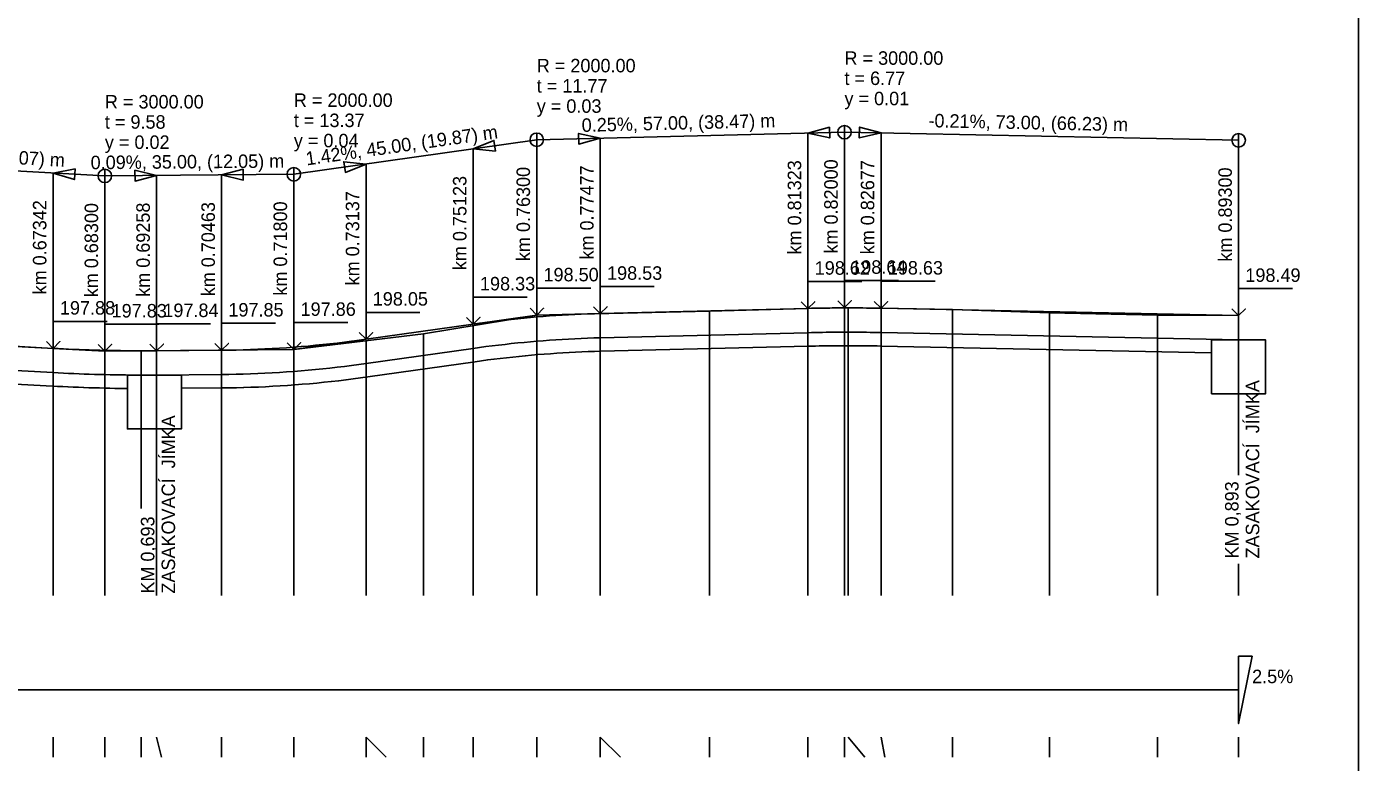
# Model space of a CAD drawing. Extents: x -51 to 53, y -74 to 15.
# Drawn here: x 28.41 to 53.08, y -60.64 to -47 of the extents above; entities that cross this region are included whole.
import ezdxf

# ---------------------------------------------------------------- set-up
doc = ezdxf.new("R2010")
doc.units = 0
for name, color, linetype in [('Implicitní', 7, 'Continuous'), ('KONSTRUKCE_L', 7, 'Continuous'), ('KOTY_L', 7, 'Continuous'), ('Nová vrstva (0)', 7, 'Continuous'), ('PR_SKLON_L', 7, 'Continuous'), ('PR_SKLON_T', 7, 'Continuous'), ('SKLON_POMERY', 7, 'Continuous'), ('TEREN_L', 7, 'Continuous'), ('V_POLYGON', 7, 'Continuous'), ('V_POLYGON_ZO', 7, 'Continuous')]:
    doc.layers.add(name, color=color, linetype=linetype)

msp = doc.modelspace()

# ---------------------------------------------------------------- linework, layer by layer
at = {"layer": 'Implicitní'}
msp.add_lwpolyline([(-51.392, -44.246), (53.079, -44.246), (53.079, -73.946), (-51.392, -73.946)], close=True, dxfattribs=at)
at = {"layer": 'KONSTRUKCE_L'}
for p, q in [((38.566, -52.789), (38.684, -52.784)), ((38.684, -52.784), (38.801, -52.779)), ((38.801, -52.779), (38.919, -52.776)), ((38.919, -52.776), (39.037, -52.772)), ((39.037, -52.772), (42.883, -52.678)), ((42.883, -52.678), (42.951, -52.676)), ((42.951, -52.676), (43.019, -52.675)), ((43.019, -52.675), (43.086, -52.674)), ((43.086, -52.674), (43.154, -52.672)), ((43.154, -52.672), (43.222, -52.671)), ((43.222, -52.671), (43.289, -52.671)), ((43.289, -52.671), (43.357, -52.67)), ((43.357, -52.67), (43.425, -52.669)), ((43.425, -52.669), (43.492, -52.669)), ((43.492, -52.669), (43.56, -52.669)), ((43.56, -52.669), (43.628, -52.669)), ((43.628, -52.669), (43.695, -52.669)), ((43.695, -52.669), (43.763, -52.669)), ((43.763, -52.669), (43.831, -52.669)), ((43.831, -52.669), (43.898, -52.67)), ((43.898, -52.67), (43.966, -52.671)), ((43.966, -52.671), (44.034, -52.672)), ((44.034, -52.672), (44.101, -52.673)), ((44.101, -52.673), (44.169, -52.674)), ((44.169, -52.674), (44.237, -52.675)), ((44.237, -52.675), (50.86, -52.811)), ((34.697, -53.251), (36.683, -52.969)), ((36.683, -52.969), (36.801, -52.952)), ((36.801, -52.952), (36.919, -52.936)), ((36.919, -52.936), (37.036, -52.921)), ((37.036, -52.921), (37.154, -52.907)), ((37.154, -52.907), (37.272, -52.894)), ((37.272, -52.894), (37.389, -52.881)), ((37.389, -52.881), (37.507, -52.868)), ((37.507, -52.868), (37.625, -52.857)), ((37.625, -52.857), (37.742, -52.846)), ((37.742, -52.846), (37.86, -52.836)), ((37.86, -52.836), (37.978, -52.826)), ((37.978, -52.826), (38.095, -52.818)), ((38.095, -52.818), (38.213, -52.809)), ((38.213, -52.809), (38.331, -52.802)), ((38.331, -52.802), (38.448, -52.795)), ((38.448, -52.795), (38.566, -52.789)), ((34.429, -53.287), (34.563, -53.27)), ((34.563, -53.27), (34.697, -53.251)), ((26.694, -53.296), (28.902, -53.418)), ((28.902, -53.418), (28.997, -53.423)), ((28.997, -53.423), (29.093, -53.428)), ((29.093, -53.428), (29.189, -53.433)), ((29.189, -53.433), (29.285, -53.437)), ((29.285, -53.437), (29.381, -53.441)), ((29.381, -53.441), (29.477, -53.444)), ((29.477, -53.444), (29.572, -53.448)), ((29.572, -53.448), (29.668, -53.451)), ((29.668, -53.451), (29.764, -53.453)), ((29.764, -53.453), (29.86, -53.456)), ((29.86, -53.456), (29.956, -53.458)), ((29.956, -53.458), (30.052, -53.46)), ((30.052, -53.46), (30.148, -53.461)), ((30.148, -53.461), (30.243, -53.462)), ((30.243, -53.462), (30.339, -53.463)), ((30.339, -53.463), (30.435, -53.464)), ((30.435, -53.464), (30.531, -53.464)), ((30.531, -53.464), (30.627, -53.464)), ((30.627, -53.464), (30.723, -53.464)), ((30.723, -53.464), (30.818, -53.463)), ((30.818, -53.463), (32.023, -53.453)), ((32.023, -53.453), (32.157, -53.451)), ((32.157, -53.451), (32.291, -53.449)), ((32.291, -53.449), (32.424, -53.445)), ((32.424, -53.445), (32.558, -53.441)), ((32.558, -53.441), (32.692, -53.436)), ((32.692, -53.436), (32.825, -53.43)), ((32.825, -53.43), (32.959, -53.423)), ((32.959, -53.423), (33.093, -53.415)), ((33.093, -53.415), (33.226, -53.406)), ((33.226, -53.406), (33.36, -53.397)), ((33.36, -53.397), (33.494, -53.386)), ((33.494, -53.386), (33.627, -53.375)), ((33.627, -53.375), (33.761, -53.362)), ((33.761, -53.362), (33.895, -53.349)), ((33.895, -53.349), (34.028, -53.335)), ((34.028, -53.335), (34.162, -53.32)), ((34.162, -53.32), (34.296, -53.304)), ((34.296, -53.304), (34.429, -53.287))]:
    msp.add_line(p, q, dxfattribs=at)
at = {"layer": 'KOTY_L'}
for p, q in [((41.06, -57.551), (41.06, -52.281)), ((42.883, -57.551), (42.883, -52.23)), ((43.56, -57.551), (43.56, -52.211)), ((43.628, -57.551), (43.628, -52.213)), ((44.237, -57.551), (44.237, -52.225)), ((45.56, -57.551), (45.56, -52.251)), ((37.86, -57.551), (37.86, -52.351)), ((39.037, -57.551), (39.037, -52.325)), ((39.037, -57.551), (39.037, -52.325)), ((47.36, -57.551), (47.36, -52.311)), ((49.36, -57.551), (49.36, -52.351)), ((50.86, -55.319), (50.86, -52.361)), ((35.76, -57.551), (35.76, -52.701)), ((36.683, -57.551), (36.683, -52.547)), ((28.902, -57.551), (28.902, -52.971)), ((29.86, -57.551), (29.86, -53.021)), ((30.531, -55.937), (30.531, -53.015)), ((30.818, -57.551), (30.818, -53.013)), ((32.023, -57.551), (32.023, -53.003)), ((33.36, -57.551), (33.36, -52.991)), ((34.697, -57.551), (34.697, -52.83)), ((34.697, -57.551), (34.697, -52.83)), ((50.86, -57.551), (50.86, -56.964)), ((28.902, -60.551), (28.902, -60.176)), ((29.86, -60.551), (29.86, -60.176)), ((30.531, -60.551), (30.531, -60.176)), ((30.906, -60.551), (30.818, -60.176)), ((32.023, -60.551), (32.023, -60.176)), ((33.36, -60.551), (33.36, -60.176)), ((34.697, -60.551), (34.697, -60.176)), ((35.072, -60.551), (34.697, -60.176)), ((35.76, -60.551), (35.76, -60.176)), ((36.683, -60.551), (36.683, -60.176)), ((37.86, -60.551), (37.86, -60.176)), ((39.037, -60.551), (39.037, -60.176)), ((39.412, -60.551), (39.037, -60.176)), ((41.06, -60.551), (41.06, -60.176)), ((42.883, -60.551), (42.883, -60.176)), ((43.56, -60.551), (43.56, -60.176)), ((43.935, -60.551), (43.628, -60.176)), ((44.31, -60.551), (44.237, -60.176)), ((45.56, -60.551), (45.56, -60.176)), ((47.36, -60.551), (47.36, -60.176)), ((49.36, -60.551), (49.36, -60.176)), ((50.86, -60.551), (50.86, -60.176))]:
    msp.add_line(p, q, dxfattribs=at)
at = {"layer": 'Nová vrstva (0)'}
for p, q in [((38.577, -53.039), (38.695, -53.034)), ((38.693, -53.034), (38.811, -53.029)), ((38.81, -53.029), (38.927, -53.025)), ((38.926, -53.025), (39.043, -53.022)), ((39.043, -53.022), (42.889, -52.928)), ((42.889, -52.928), (42.957, -52.926)), ((42.956, -52.926), (43.024, -52.925)), ((43.023, -52.925), (43.091, -52.923)), ((43.091, -52.923), (43.158, -52.922)), ((43.158, -52.922), (43.225, -52.921)), ((43.225, -52.921), (43.292, -52.921)), ((43.292, -52.921), (43.359, -52.92)), ((43.359, -52.92), (43.427, -52.919)), ((43.426, -52.919), (43.494, -52.919)), ((43.493, -52.919), (43.561, -52.919)), ((43.56, -52.919), (43.628, -52.919)), ((43.627, -52.919), (43.695, -52.919)), ((43.694, -52.919), (43.762, -52.919)), ((43.762, -52.919), (43.829, -52.919)), ((43.829, -52.919), (43.896, -52.92)), ((43.896, -52.92), (43.963, -52.921)), ((43.963, -52.921), (44.03, -52.922)), ((44.03, -52.922), (44.098, -52.923)), ((44.097, -52.923), (44.165, -52.924)), ((44.164, -52.924), (44.232, -52.925)), ((44.232, -52.925), (50.36, -53.051)), ((34.732, -53.499), (36.719, -53.216)), ((36.718, -53.216), (36.836, -53.2)), ((36.834, -53.2), (36.952, -53.184)), ((36.95, -53.184), (37.068, -53.169)), ((37.067, -53.17), (37.184, -53.155)), ((37.183, -53.155), (37.3, -53.142)), ((37.299, -53.142), (37.417, -53.129)), ((37.415, -53.129), (37.533, -53.117)), ((37.531, -53.117), (37.649, -53.106)), ((37.648, -53.106), (37.765, -53.095)), ((37.764, -53.095), (37.882, -53.085)), ((37.88, -53.085), (37.998, -53.076)), ((37.996, -53.076), (38.114, -53.067)), ((38.112, -53.067), (38.23, -53.059)), ((38.229, -53.059), (38.346, -53.052)), ((38.345, -53.052), (38.463, -53.045)), ((38.461, -53.045), (38.579, -53.039)), ((34.462, -53.535), (34.596, -53.518)), ((34.597, -53.517), (34.731, -53.499)), ((26.681, -53.546), (28.888, -53.668)), ((28.888, -53.668), (28.984, -53.673)), ((28.985, -53.673), (29.081, -53.678)), ((29.081, -53.678), (29.177, -53.682)), ((29.178, -53.682), (29.274, -53.687)), ((29.275, -53.687), (29.371, -53.691)), ((29.371, -53.691), (29.467, -53.694)), ((29.468, -53.694), (29.564, -53.698)), ((29.565, -53.698), (29.66, -53.701)), ((29.661, -53.701), (29.757, -53.703)), ((29.758, -53.703), (29.854, -53.706)), ((29.855, -53.706), (29.95, -53.708)), ((29.951, -53.708), (30.047, -53.71)), ((30.048, -53.71), (30.144, -53.711)), ((30.144, -53.711), (30.279, -53.713)), ((31.279, -53.709), (32.026, -53.703)), ((32.026, -53.703), (32.16, -53.701)), ((32.162, -53.701), (32.295, -53.699)), ((32.297, -53.698), (32.431, -53.695)), ((32.432, -53.695), (32.566, -53.691)), ((32.568, -53.691), (32.701, -53.686)), ((32.703, -53.685), (32.837, -53.679)), ((32.838, -53.679), (32.972, -53.672)), ((32.974, -53.672), (33.107, -53.664)), ((33.109, -53.664), (33.243, -53.656)), ((33.244, -53.656), (33.378, -53.646)), ((33.38, -53.646), (33.513, -53.635)), ((33.515, -53.635), (33.649, -53.624)), ((33.65, -53.624), (33.784, -53.611)), ((33.786, -53.611), (33.919, -53.598)), ((33.921, -53.598), (34.054, -53.584)), ((34.056, -53.583), (34.19, -53.568)), ((34.191, -53.568), (34.325, -53.552)), ((34.327, -53.552), (34.46, -53.535))]:
    msp.add_line(p, q, dxfattribs=at)
for points in [[(50.36, -52.811), (51.36, -52.811), (51.36, -53.811), (50.36, -53.811)], [(30.279, -53.463), (31.279, -53.463), (31.279, -54.463), (30.279, -54.463)]]:
    msp.add_lwpolyline(points, close=True, dxfattribs=at)
at = {"layer": 'PR_SKLON_L'}
msp.add_line((8.36, -59.301), (50.86, -59.301), dxfattribs=at)
msp.add_lwpolyline([(50.86, -59.301), (50.86, -58.676), (51.11, -58.676), (50.86, -59.926)], close=True, dxfattribs=at)
at = {"layer": 'SKLON_POMERY'}
for p, q in [((43.56, -48.961), (43.56, -48.836)), ((37.86, -49.101), (43.56, -48.961)), ((37.86, -49.101), (37.86, -48.976)), ((39.037, -52.322), (39.037, -49.072)), ((42.883, -52.228), (42.883, -48.978)), ((43.56, -52.211), (43.56, -48.961)), ((43.56, -48.961), (50.86, -49.111)), ((44.237, -52.225), (44.237, -48.975)), ((50.86, -49.111), (50.86, -48.986)), ((33.36, -49.741), (37.86, -49.101)), ((36.683, -52.519), (36.683, -49.269)), ((37.86, -52.351), (37.86, -49.101)), ((50.86, -52.361), (50.86, -49.111)), ((25.16, -49.511), (29.86, -49.771)), ((34.697, -52.801), (34.697, -49.551)), ((28.902, -52.968), (28.902, -49.718)), ((29.86, -49.771), (29.86, -49.646)), ((29.86, -49.771), (33.36, -49.741)), ((29.86, -53.021), (29.86, -49.771)), ((30.818, -53.013), (30.818, -49.763)), ((32.023, -53.003), (32.023, -49.753)), ((33.36, -49.741), (33.36, -49.616)), ((33.36, -52.991), (33.36, -49.741))]:
    msp.add_line(p, q, dxfattribs=at)
for points in [[(39.037, -49.072), (38.639, -49.182), (38.634, -48.982), (39.037, -49.072)], [(42.883, -48.978), (43.286, -49.068), (43.281, -48.868), (42.883, -48.978)], [(44.237, -48.975), (43.835, -49.067), (43.839, -48.867), (44.237, -48.975)], [(36.683, -49.269), (37.093, -49.311), (37.065, -49.113), (36.683, -49.269)], [(34.697, -49.551), (34.315, -49.706), (34.286, -49.508), (34.697, -49.551)], [(28.902, -49.718), (29.296, -49.84), (29.307, -49.64), (28.902, -49.718)], [(30.818, -49.763), (30.419, -49.866), (30.418, -49.666), (30.818, -49.763)], [(32.023, -49.753), (32.424, -49.849), (32.423, -49.649), (32.023, -49.753)]]:
    msp.add_lwpolyline(points, close=True, dxfattribs=at)
for points in [[(42.758, -52.103), (42.883, -52.228), (43.008, -52.103), (42.883, -52.228), (42.883, -51.728), (43.883, -51.728)], [(43.435, -52.086), (43.56, -52.211), (43.685, -52.086), (43.56, -52.211), (43.56, -51.711), (44.56, -51.711)], [(44.112, -52.1), (44.237, -52.225), (44.362, -52.1), (44.237, -52.225), (44.237, -51.725), (45.237, -51.725)], [(36.558, -52.394), (36.683, -52.519), (36.808, -52.394), (36.683, -52.519), (36.683, -52.019), (37.683, -52.019)], [(37.735, -52.226), (37.86, -52.351), (37.985, -52.226), (37.86, -52.351), (37.86, -51.851), (38.86, -51.851)], [(38.912, -52.197), (39.037, -52.322), (39.162, -52.197), (39.037, -52.322), (39.037, -51.822), (40.037, -51.822)], [(50.735, -52.236), (50.86, -52.361), (50.985, -52.236), (50.86, -52.361), (50.86, -51.861), (51.86, -51.861)], [(28.777, -52.843), (28.902, -52.968), (29.027, -52.843), (28.902, -52.968), (28.902, -52.468), (29.902, -52.468)], [(29.735, -52.896), (29.86, -53.021), (29.985, -52.896), (29.86, -53.021), (29.86, -52.521), (30.86, -52.521)], [(30.693, -52.888), (30.818, -53.013), (30.943, -52.888), (30.818, -53.013), (30.818, -52.513), (31.818, -52.513)], [(31.898, -52.878), (32.023, -53.003), (32.148, -52.878), (32.023, -53.003), (32.023, -52.503), (33.023, -52.503)], [(33.235, -52.866), (33.36, -52.991), (33.485, -52.866), (33.36, -52.991), (33.36, -52.491), (34.36, -52.491)], [(34.572, -52.676), (34.697, -52.801), (34.822, -52.676), (34.697, -52.801), (34.697, -52.301), (35.697, -52.301)]]:
    msp.add_lwpolyline(points, dxfattribs=at)
for centre in [(43.56, -48.961), (37.86, -49.101), (50.86, -49.111), (29.86, -49.771), (33.36, -49.741)]:
    msp.add_circle(centre, 0.125, dxfattribs=at)
at = {"layer": 'TEREN_L'}
for p, q in [((37.86, -52.351), (41.06, -52.281)), ((41.06, -52.281), (43.56, -52.211)), ((43.56, -52.211), (45.56, -52.251)), ((45.56, -52.251), (47.36, -52.311)), ((35.76, -52.701), (37.86, -52.351)), ((47.36, -52.311), (49.36, -52.351)), ((49.36, -52.351), (50.86, -52.361)), ((33.36, -52.991), (35.76, -52.701)), ((27.36, -52.891), (29.86, -53.021)), ((29.86, -53.021), (33.36, -52.991))]:
    msp.add_line(p, q, dxfattribs=at)
at = {"layer": 'V_POLYGON'}
for p, q in [((39.037, -52.322), (42.883, -52.228)), ((44.237, -52.225), (50.86, -52.361)), ((34.697, -52.801), (36.683, -52.519)), ((26.694, -52.846), (28.902, -52.968)), ((30.818, -53.013), (32.023, -53.003))]:
    msp.add_line(p, q, dxfattribs=at)
for points in [[(42.883, -52.228), (42.951, -52.226), (43.019, -52.225), (43.086, -52.224), (43.154, -52.222), (43.222, -52.221), (43.289, -52.221), (43.357, -52.22), (43.425, -52.219), (43.492, -52.219), (43.56, -52.219), (43.628, -52.219), (43.695, -52.219), (43.763, -52.219), (43.831, -52.219), (43.898, -52.22), (43.966, -52.221), (44.034, -52.222), (44.101, -52.223), (44.169, -52.224), (44.237, -52.225)], [(36.683, -52.519), (36.801, -52.502), (36.919, -52.486), (37.036, -52.471), (37.154, -52.457), (37.272, -52.444), (37.389, -52.431), (37.507, -52.418), (37.625, -52.407), (37.742, -52.396), (37.86, -52.386), (37.978, -52.376), (38.095, -52.368), (38.213, -52.359), (38.331, -52.352), (38.448, -52.345), (38.566, -52.339), (38.684, -52.334), (38.801, -52.329), (38.919, -52.326), (39.037, -52.322)], [(28.902, -52.968), (28.997, -52.973), (29.093, -52.978), (29.189, -52.983), (29.285, -52.987), (29.381, -52.991), (29.477, -52.994), (29.572, -52.998), (29.668, -53.001), (29.764, -53.003), (29.86, -53.006), (29.956, -53.008), (30.052, -53.01), (30.148, -53.011), (30.243, -53.012), (30.339, -53.013), (30.435, -53.014), (30.531, -53.014), (30.627, -53.014), (30.723, -53.014), (30.818, -53.013)], [(32.023, -53.003), (32.157, -53.001), (32.291, -52.999), (32.424, -52.995), (32.558, -52.991), (32.692, -52.986), (32.825, -52.98), (32.959, -52.973), (33.093, -52.965), (33.226, -52.956), (33.36, -52.947), (33.494, -52.936), (33.627, -52.925), (33.761, -52.912), (33.895, -52.899), (34.028, -52.885), (34.162, -52.87), (34.296, -52.854), (34.429, -52.837), (34.563, -52.82), (34.697, -52.801)]]:
    msp.add_lwpolyline(points, dxfattribs=at)
at = {"layer": 'V_POLYGON_ZO'}
for p, q in [((42.883, -52.228), (43.56, -52.211)), ((43.56, -52.211), (44.237, -52.225)), ((36.683, -52.519), (37.86, -52.351)), ((37.86, -52.351), (39.037, -52.322)), ((28.902, -52.968), (29.86, -53.021)), ((29.86, -53.021), (30.818, -53.013)), ((32.023, -53.003), (33.36, -52.991)), ((33.36, -52.991), (34.697, -52.801))]:
    msp.add_line(p, q, dxfattribs=at)

# ---------------------------------------------------------------- texts
at = {"layer": 'Nová vrstva (0)'}
for s, p in [('ZASAKOVACÍ  JÍMKA', (51.243, -56.864)), ('ZASAKOVACÍ  JÍMKA', (31.161, -57.516)), ('KM 0,893', (50.859, -56.864)), ('KM 0,693', (30.777, -57.516))]:
    msp.add_text(s, height=0.25, rotation=90, dxfattribs=at).set_placement(p)
at = {"layer": 'PR_SKLON_T'}
msp.add_text('2.5%', height=0.25, dxfattribs=at).set_placement((51.11, -59.176))
at = {"layer": 'SKLON_POMERY'}
for s, p in [('R = 2000.00', (37.86, -47.851)), ('R = 3000.00', (43.56, -47.711)), ('t = 6.77', (43.56, -48.086)), ('t = 11.77', (37.86, -48.226)), ('R = 3000.00', (29.86, -48.521)), ('R = 2000.00', (33.36, -48.491)), ('y = 0.03', (37.86, -48.601)), ('y = 0.01', (43.56, -48.461)), ('t = 9.58', (29.86, -48.896)), ('t = 13.37', (33.36, -48.866)), ('y = 0.02', (29.86, -49.271)), ('y = 0.04', (33.36, -49.241)), ('198.50', (37.985, -51.726)), ('198.53', (39.162, -51.697)), ('198.62', (43.008, -51.603)), ('198.64', (43.685, -51.586)), ('198.63', (44.362, -51.6)), ('198.49', (50.985, -51.736)), ('198.33', (36.808, -51.894)), ('198.05', (34.822, -52.176)), ('197.88', (29.027, -52.343)), ('197.83', (29.985, -52.396)), ('197.84', (30.943, -52.388)), ('197.85', (32.148, -52.378)), ('197.86', (33.485, -52.366))]:
    msp.add_text(s, height=0.25, dxfattribs=at).set_placement(p)
for s, rotation, p in [('0.25%, 57.00, (38.47) m', 1.407, (38.695, -48.956)), ('-0.21%, 73.00, (66.23) m', 358.8229, (45.113, -48.868)), ('1.42%, 45.00, (19.87) m', 8.0945, (33.6, -49.578)), ('-0.55%, 47.00, (22.07) m', 356.8337, (25.42, -49.4)), ('0.09%, 35.00, (12.05) m', 0.4911, (29.597, -49.648)), ('km 0.81323', 90, (42.758, -51.228)), ('km 0.82000', 90, (43.435, -51.211)), ('km 0.82677', 90, (44.112, -51.225)), ('km 0.75123', 90, (36.558, -51.519)), ('km 0.76300', 90, (37.735, -51.351)), ('km 0.77477', 90, (38.912, -51.322)), ('km 0.89300', 90, (50.735, -51.361)), ('km 0.73137', 90, (34.572, -51.801)), ('km 0.67342', 90, (28.777, -51.968)), ('km 0.68300', 90, (29.735, -52.021)), ('km 0.69258', 90, (30.693, -52.013)), ('km 0.70463', 90, (31.898, -52.003)), ('km 0.71800', 90, (33.235, -51.991))]:
    msp.add_text(s, height=0.25, rotation=rotation, dxfattribs=at).set_placement(p)

doc.saveas('drawing.dxf')
